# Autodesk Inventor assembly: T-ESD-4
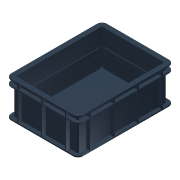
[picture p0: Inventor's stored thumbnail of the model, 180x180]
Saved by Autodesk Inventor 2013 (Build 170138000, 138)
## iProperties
Created: 2004-11
Part Number: T-ESD-4
Document SubType Name: Assembly
Designer: Autodesk, Inc.
Manufacturer: Standard
Standards Organization: Custom
Mass: 2161.22 g
Surface Area: 9822.36 cm^2
Volume: 2161.22 cm^3
Density: 1 g/cm^3
CAGE: 1LJX3
Dept. ID: Product Design
Description #2: ---
Finish #1: ---
Finish #2: ---
Material ID: ---
Project Number: ---
Author: Autodesk, Inc.
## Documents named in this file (4)
- Z:\_DATEN\Test Station\Components\Standard Tote.iam
- Z:\_DATEN\Test Station\Components\Tote Base.ipt
- Z:\_DATEN\Test Station\Components\Slots Part.ipt
- Z:\_DATEN\Test Station\Components\Slots Part 2.ipt
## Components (5 placed, 3 different names)
1. Tote Base:1 — Angle:1, Flush:1, Mate:2, Mate:3, Flush:3, Mate:6, Mate:8
2. Slots Part:1 — Mate:3, Flush:2
3. Slots Part:2 — Flush:1, Mate:2, Flush:2
4. Slots Part 2:1 — Flush:3, Mate:6, Flush:4
5. Slots Part 2:2 — Mate:8, Flush:4
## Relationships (9: Flush 4, Mate 4, Angle 1)
- Angle:1: Tote Base:1
- Flush:1: Tote Base:1 ↔ Slots Part:2
- Mate:2: Tote Base:1 ↔ Slots Part:2
- Mate:3: Tote Base:1 ↔ Slots Part:1
- Flush:2: Slots Part:1 ↔ Slots Part:2
- Flush:3: Tote Base:1 ↔ Slots Part 2:1
- Mate:6: Tote Base:1 ↔ Slots Part 2:1
- Mate:8: Tote Base:1 ↔ Slots Part 2:2
- Flush:4: Slots Part 2:1 ↔ Slots Part 2:2
